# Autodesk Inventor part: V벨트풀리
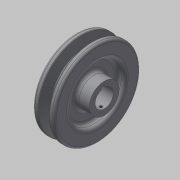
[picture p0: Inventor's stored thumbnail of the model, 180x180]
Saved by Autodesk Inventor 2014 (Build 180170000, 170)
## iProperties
Created: 2015-11
Part Number: V벨트풀리
Material: 강철, 탄소
Document SubType Name: Modeling
Designer: mduedu
Density: 1 g/cm^3
Appearance: Default
Author: mduedu
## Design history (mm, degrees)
sketch "스케치1"
  geometry: L1 (-9.5, 0)-(9.5, 0); L2 (0, 0)-(0, 37.7); L3 (-4.825, 37.7)-(-9.5, 37.7); L4 (-9.5, 37.7)-(-9.5, 0); L5 (0, 28.7)-(-2.074, 28.7); L6 (-2.074, 28.7)-(-4.825, 37.7); L7 (4.825, 37.7)-(9.5, 37.7); L8 (9.5, 37.7)-(9.5, 0); L9 (0, 28.7)-(2.074, 28.7); L10 (2.074, 28.7)-(4.825, 37.7); L11 (-9.5, 35)-(9.5, 35); 3 further points
  constraints: 22 end point, 7 point on line, 4 perpendicular, 3 symmetric about line, 1 coincident, 1 horizontal, 1 horizontal alignment, 1 midpoint, 1 vertical
  dimensions: "d0" = 19 distance of L1.start L1.end; "d2" = 75.4 diameter of L2.end L1 (derived); "d3" = 34 deg angle of L10 L6; "d4" = 6.3 distance between parallel lines of L11 L9; "d5" = 2.7 distance between parallel lines of L7 L11; "d6" = 8 distance of point (4, 35) point (-4, 35); "d7" = 70 diameter of L11 L1
revolve "회전1" sketch "스케치1" stored, may be unused: angle "d8" = 90 deg
sketch "스케치2"
  geometry: C1 r 24 at (0, 0); C2 r 13 at (0, 0); 1 further point
  constraints: 2 centre point, 2 coincident
  dimensions: "d9" = 48 diameter of C1; "d10" = 26 diameter of C2
extrude "돌출1" cut sketch "스케치2" distance "d11" = 6; taper "d12" = 0 deg
extrude "돌출3" join sketch "스케치2" distance "d37" = 6; taper "d38" = 0 deg
fillet "모깎기1" dims "d13" = 3
fillet "모깎기2" dims "d14" = 3
fillet "모깎기3" dims "d15" = 1, "d16" = 0.5, "d17" = 2
hole "구멍1" diameter "d20" = 16; stored, may be unused: countersink angle "d24" = 90 deg, drill point angle "d26" = 118 deg; dims "d21" = 6, "d22" = 4, "d23" = 2, "d25" = 8, "d53" = 10, "d54" = 10
sketch "스케치3"
  geometry: L1 (-2.5, 0)-(2.5, 0); L2 (2.5, 0)-(2.5, 10.3); L3 (2.5, 10.3)-(-2.5, 10.3); L4 (-2.5, 10.3)-(-2.5, 0); 2 further points
  constraints: 8 end point, 2 parallel, 1 coincident, 1 horizontal, 1 midpoint, 1 perpendicular
  dimensions: "d27" = 5 distance of L2.end L3.end; "d29" = 10.3 distance of L3.end L1.start
extrude "돌출2" cut sketch "스케치3" stored distance "d30" = 6; taper "d31" = 0 deg
chamfer "모따기1" distance "d32" = 1; stored, may be unused: second distance "d33" = 2, angle "d34" = 45 deg
node "작업 평면1"
sketch "스케치4"
  geometry: L1 (19, -27)-(19, 27) reference; 2 further points
  constraints: 1 horizontal alignment
  dimensions: "d52" = 22 distance from line of L1 point (-3, 0)
hole "구멍2" sketch "스케치4" at (-3, 0) diameter "d42" = 2.459; stored, may be unused: countersink angle "d46" = 90 deg, drill point angle "d48" = 118 deg; dims "d43" = 6, "d44" = 4, "d45" = 2, "d47" = 8
node "솔리드1"
mirror "대칭1"
